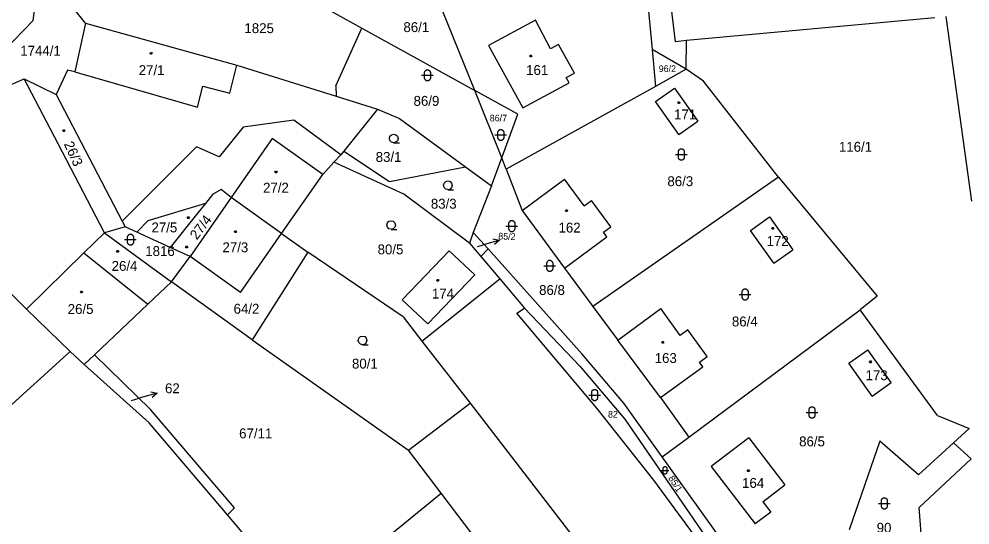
# Model space of a CAD drawing. Extents: x -799786 to -795190, y -1021716 to -1017834.
# Drawn here: x -797930.9 to -797767.7, y -1019141.2 to -1019054.3 of the extents above; entities that cross this region are included whole.
import ezdxf

# ---------------------------------------------------------------- set-up
doc = ezdxf.new("R2010")
doc.units = 0
for name, color, linetype in [('Default', 7, 'Continuous'), ('KN_HRANICE', 7, 'Continuous'), ('KN_KULTURY', 7, 'Continuous'), ('KN_PARCELY', 7, 'Continuous'), ('KN_SLUCKY', 7, 'Continuous')]:
    doc.layers.add(name, color=color, linetype=linetype)

# ---------------------------------------------------------------- blocks, each defined once
blk = doc.blocks.new('304')
at = {"layer": 'Default'}
blk.add_lwpolyline([(0, 0), (-0.38, 0.1), (-0.65, 0.37), (-0.75, 0.74), (-0.65, 1.11), (-0.38, 1.38), (-0.01, 1.48), (0.36, 1.38), (0.63, 1.11), (0.73, 0.73), (0.63, 0.35), (0.36, 0.08), (-0.02, -0.02), (0.98, -0.02)], dxfattribs=at)
blk = doc.blocks.new('316')
at = {"layer": 'Default'}
for points in [[(-0.5, 1.5), (-0.4, 1.79), (-0.15, 1.97), (0.16, 1.97), (0.41, 1.79), (0.51, 1.5), (0.51, 0.5), (0.41, 0.21), (0.16, 0.03), (-0.15, 0.03), (-0.4, 0.21), (-0.5, 0.5), (-0.5, 1.5)], [(-1, 1), (0.27, 1), (1, 1)]]:
    blk.add_lwpolyline(points, dxfattribs=at)
blk = doc.blocks.new('NAHRADNI_SYMBOL')
at = {"layer": 'Default'}
blk.add_lwpolyline([(0.09, 0.15), (0.18, 0), (0.09, -0.15), (-0.09, -0.15), (-0.18, 0), (-0.09, 0.15), (0.09, 0.15)], dxfattribs=at)
blk = doc.blocks.new('10292')
at = {"layer": 'Default'}
blk.add_line((0, 3), (0, 0), dxfattribs=at)
blk.add_lwpolyline([(-0.5, 2), (0, 3), (0.5, 2)], dxfattribs=at)
blk = doc.blocks.new('402')
at = {"layer": 'Default'}
blk.add_lwpolyline([(0.09, 0.15), (0.18, 0), (0.09, -0.15), (-0.09, -0.15), (-0.18, 0), (-0.09, 0.15), (0.09, 0.15)], dxfattribs=at)

msp = doc.modelspace()

# ---------------------------------------------------------------- linework, layer by layer
at = {"layer": 'KN_HRANICE'}
for p, q in [((-797852.67, -1019066.58), (-797869.05, -1019025.87)), ((-797818.22, -1019058.17), (-797821.18, -1019032.56)), ((-797928.48, -1019054.53), (-797927.24, -1019045.89)), ((-797823.64, -1019044.95), (-797822.2, -1019059.5)), ((-797883.29, -1019049.58), (-797872.02, -1019055.83)), ((-797919.48, -1019055.01), (-797921.61, -1019052.33)), ((-797842.24, -1019054.46), (-797850.27, -1019058.84)), ((-797839.67, -1019059.39), (-797842.24, -1019054.46)), ((-797773.7, -1019054.09), (-797816.3, -1019057.99)), ((-797767.35, -1019085.59), (-797771.72, -1019053.85)), ((-797933.64, -1019059.89), (-797928.48, -1019054.53)), ((-797919.48, -1019055.01), (-797921.28, -1019063.37)), ((-797919.48, -1019055.01), (-797893.51, -1019062.22)), ((-797876.5, -1019065.73), (-797872.02, -1019055.83)), ((-797872.02, -1019055.83), (-797852.67, -1019066.58)), ((-797850.27, -1019058.84), (-797844.43, -1019069.56)), ((-797838.26, -1019058.63), (-797839.67, -1019059.39)), ((-797835.56, -1019063.59), (-797838.26, -1019058.63)), ((-797816.3, -1019057.99), (-797818.22, -1019058.17)), ((-797816.38, -1019062.91), (-797816.3, -1019057.99)), ((-797816.38, -1019062.91), (-797822.2, -1019059.5)), ((-797822.2, -1019059.5), (-797821.66, -1019065.85)), ((-797893.51, -1019062.22), (-797876.43, -1019067.54)), ((-797922.55, -1019063.04), (-797924.49, -1019067.25)), ((-797921.28, -1019063.37), (-797922.55, -1019063.04)), ((-797836.96, -1019064.35), (-797835.56, -1019063.59)), ((-797816.38, -1019062.91), (-797821.66, -1019065.85)), ((-797813.4, -1019064.96), (-797816.38, -1019062.91)), ((-797942.17, -1019069.78), (-797930, -1019064.56)), ((-797930, -1019064.56), (-797924.49, -1019067.25)), ((-797924.18, -1019075.72), (-797930, -1019064.56)), ((-797876.5, -1019065.73), (-797876.43, -1019067.54)), ((-797821.66, -1019065.85), (-797847.25, -1019080.08)), ((-797844.43, -1019069.56), (-797836.48, -1019065.23)), ((-797836.48, -1019065.23), (-797836.96, -1019064.35)), ((-797800.54, -1019081.45), (-797813.4, -1019064.96)), ((-797924.49, -1019067.25), (-797913.17, -1019088.98)), ((-797845.27, -1019070.6), (-797852.67, -1019066.58)), ((-797848.03, -1019078.14), (-797852.67, -1019066.58)), ((-797821.62, -1019068.47), (-797818.35, -1019066.17)), ((-797818.35, -1019066.17), (-797814.38, -1019071.82)), ((-797876.43, -1019067.54), (-797869.33, -1019069.75)), ((-797817.65, -1019074.12), (-797821.62, -1019068.47)), ((-797869.33, -1019069.75), (-797875.15, -1019076.95)), ((-797869.33, -1019069.75), (-797865.57, -1019071.38)), ((-797848.03, -1019078.14), (-797845.27, -1019070.6)), ((-797883.72, -1019071.64), (-797892.43, -1019072.87)), ((-797875.67, -1019077.59), (-797883.72, -1019071.64)), ((-797865.57, -1019071.38), (-797854.22, -1019079.67)), ((-797817.65, -1019074.12), (-797814.38, -1019071.82)), ((-797892.43, -1019072.87), (-797896.5, -1019077.93)), ((-797916.22, -1019090.98), (-797924.18, -1019075.72)), ((-797900.41, -1019076.21), (-797913.17, -1019088.98)), ((-797896.5, -1019077.93), (-797900.41, -1019076.21)), ((-797875.15, -1019076.95), (-797875.67, -1019077.59)), ((-797878.76, -1019080.97), (-797876.83, -1019078.86)), ((-797876.83, -1019078.86), (-797875.67, -1019077.59)), ((-797864.84, -1019084.36), (-797876.83, -1019078.86)), ((-797849.78, -1019082.91), (-797848.03, -1019078.14)), ((-797847.25, -1019080.08), (-797848.03, -1019078.14)), ((-797854.22, -1019079.67), (-797849.78, -1019082.91)), ((-797847.25, -1019080.08), (-797844.54, -1019087.17)), ((-797885.82, -1019091.1), (-797878.76, -1019080.97)), ((-797844.54, -1019087.17), (-797837.24, -1019081.81)), ((-797833.88, -1019086.38), (-797837.24, -1019081.81)), ((-797800.54, -1019081.45), (-797832.38, -1019103.67)), ((-797800.54, -1019081.45), (-797783.57, -1019101.88)), ((-797896.16, -1019083.58), (-797897.65, -1019084.44)), ((-797894.47, -1019084.92), (-797896.16, -1019083.58)), ((-797849.78, -1019082.91), (-797852.91, -1019090.95)), ((-797894.47, -1019084.92), (-797901.53, -1019095.05)), ((-797897.65, -1019084.44), (-797898.89, -1019085.97)), ((-797885.82, -1019091.1), (-797894.47, -1019084.92)), ((-797853.58, -1019092.77), (-797864.84, -1019084.36)), ((-797833.88, -1019086.38), (-797832.59, -1019085.43)), ((-797829.28, -1019089.95), (-797832.59, -1019085.43)), ((-797898.89, -1019085.97), (-797908.77, -1019088.92)), ((-797898.89, -1019085.97), (-797900.18, -1019087.58)), ((-797900.18, -1019087.58), (-797904.91, -1019093.5)), ((-797844.54, -1019087.17), (-797837.27, -1019097.06)), ((-797805.32, -1019090.58), (-797802.05, -1019088.28)), ((-797802.05, -1019088.28), (-797798.08, -1019093.93)), ((-797912.66, -1019089.96), (-797916.22, -1019090.98)), ((-797913.17, -1019088.98), (-797912.66, -1019089.96)), ((-797910.68, -1019090.87), (-797912.66, -1019089.96)), ((-797910.68, -1019090.87), (-797908.77, -1019088.92)), ((-797830.57, -1019090.89), (-797829.28, -1019089.95)), ((-797916.22, -1019090.98), (-797919.74, -1019094.43)), ((-797916.22, -1019090.98), (-797904.71, -1019099.44)), ((-797904.91, -1019093.5), (-797910.68, -1019090.87)), ((-797892.88, -1019101.23), (-797885.82, -1019091.1)), ((-797885.82, -1019091.1), (-797881.32, -1019094.34)), ((-797852.91, -1019090.95), (-797853.58, -1019092.77)), ((-797850.38, -1019093.78), (-797852.91, -1019090.95)), ((-797837.27, -1019097.06), (-797829.98, -1019091.7)), ((-797829.98, -1019091.7), (-797830.57, -1019090.89)), ((-797801.35, -1019096.23), (-797805.32, -1019090.58)), ((-797901.53, -1019095.05), (-797904.91, -1019093.5)), ((-797853.58, -1019092.77), (-797851.62, -1019095.09)), ((-797919.74, -1019094.43), (-797929.59, -1019104.1)), ((-797919.74, -1019094.43), (-797908.76, -1019103.28)), ((-797904.71, -1019099.44), (-797901.53, -1019095.05)), ((-797892.88, -1019101.23), (-797901.53, -1019095.05)), ((-797881.32, -1019094.34), (-797890.88, -1019109.4)), ((-797864.94, -1019105.46), (-797881.32, -1019094.34)), ((-797857.07, -1019094.11), (-797865.14, -1019102.54)), ((-797852.66, -1019098.2), (-797857.07, -1019094.11)), ((-797851.62, -1019095.09), (-797850.38, -1019093.78)), ((-797851.62, -1019095.09), (-797848.38, -1019098.9)), ((-797834.2, -1019111.83), (-797850.38, -1019093.78)), ((-797801.35, -1019096.23), (-797798.08, -1019093.93)), ((-797852.66, -1019098.2), (-797860.73, -1019106.63)), ((-797837.27, -1019097.06), (-797832.38, -1019103.67)), ((-797934.34, -1019099.45), (-797929.59, -1019104.1)), ((-797904.71, -1019099.44), (-797908.76, -1019103.28)), ((-797890.88, -1019109.4), (-797904.71, -1019099.44)), ((-797861.73, -1019109.61), (-797848.38, -1019098.9)), ((-797848.38, -1019098.9), (-797844.12, -1019103.92)), ((-797908.76, -1019103.28), (-797917.9, -1019111.94)), ((-797860.73, -1019106.63), (-797865.14, -1019102.54)), ((-797783.57, -1019101.88), (-797786.49, -1019104.25)), ((-797929.59, -1019104.1), (-797922.11, -1019111.42)), ((-797845.41, -1019104.78), (-797844.12, -1019103.92)), ((-797831.7, -1019121.13), (-797845.41, -1019104.78)), ((-797844.12, -1019103.92), (-797834.61, -1019113.9)), ((-797832.38, -1019103.67), (-797828.1, -1019109.45)), ((-797828.1, -1019109.45), (-797820.73, -1019103.98)), ((-797817.38, -1019108.62), (-797820.73, -1019103.98)), ((-797815.93, -1019126.08), (-797786.49, -1019104.25)), ((-797773.22, -1019122.38), (-797786.49, -1019104.25)), ((-797864.94, -1019105.46), (-797861.73, -1019109.61)), ((-797816.08, -1019107.68), (-797817.38, -1019108.62)), ((-797812.78, -1019112.26), (-797816.08, -1019107.68)), ((-797890.88, -1019109.4), (-797864.05, -1019128.36)), ((-797861.73, -1019109.61), (-797853.47, -1019120.29)), ((-797820.8, -1019119.29), (-797828.1, -1019109.45)), ((-797939.64, -1019127.27), (-797922.11, -1019111.42)), ((-797919.69, -1019113.6), (-797922.11, -1019111.42)), ((-797788.43, -1019113.39), (-797785.16, -1019111.09)), ((-797781.19, -1019116.74), (-797785.16, -1019111.09)), ((-797917.9, -1019111.94), (-797919.69, -1019113.6)), ((-797908.3, -1019121.34), (-797917.9, -1019111.94)), ((-797827.05, -1019120.24), (-797834.2, -1019111.83)), ((-797814.08, -1019113.2), (-797812.78, -1019112.26)), ((-797813.49, -1019114.01), (-797814.08, -1019113.2)), ((-797908.56, -1019123.66), (-797919.69, -1019113.6)), ((-797834.61, -1019113.9), (-797826.91, -1019123.02)), ((-797820.8, -1019119.29), (-797813.49, -1019114.01)), ((-797784.46, -1019119.04), (-797788.43, -1019113.39)), ((-797784.46, -1019119.04), (-797781.19, -1019116.74)), ((-797820.8, -1019119.29), (-797815.93, -1019126.08)), ((-797893.87, -1019138.25), (-797908.3, -1019121.34)), ((-797864.05, -1019128.36), (-797853.47, -1019120.29)), ((-797853.47, -1019120.29), (-797769.25, -1019229.18)), ((-797821.92, -1019133.49), (-797831.7, -1019121.13)), ((-797820.48, -1019129.46), (-797827.05, -1019120.24)), ((-797826.91, -1019123.02), (-797788.58, -1019178.77)), ((-797773.22, -1019122.38), (-797767.81, -1019124.62)), ((-797895.08, -1019139.44), (-797908.56, -1019123.66)), ((-797767.81, -1019124.62), (-797770.51, -1019127.09)), ((-797820.48, -1019129.46), (-797815.93, -1019126.08)), ((-797805.6, -1019126.23), (-797812.06, -1019131.13)), ((-797805.6, -1019126.23), (-797799.46, -1019134.27)), ((-797783.1, -1019126.77), (-797788.38, -1019142.03)), ((-797776.48, -1019132.55), (-797783.1, -1019126.77)), ((-797770.51, -1019127.09), (-797776.48, -1019132.55)), ((-797767.46, -1019129.82), (-797770.51, -1019127.09)), ((-797858.44, -1019135.72), (-797864.05, -1019128.36)), ((-797787.5, -1019175.75), (-797820.48, -1019129.46)), ((-797812.06, -1019131.13), (-797804.51, -1019141.01)), ((-797776.38, -1019138.19), (-797767.46, -1019129.82)), ((-797788.58, -1019178.77), (-797821.92, -1019133.49)), ((-797803.2, -1019137.2), (-797799.46, -1019134.27)), ((-797881.99, -1019154.95), (-797858.44, -1019135.72)), ((-797814.48, -1019193.44), (-797858.44, -1019135.72)), ((-797803.2, -1019137.2), (-797801.84, -1019138.98)), ((-797895.08, -1019139.44), (-797893.87, -1019138.25)), ((-797801.84, -1019138.98), (-797804.51, -1019141.01)), ((-797775.5, -1019150.13), (-797776.38, -1019138.19)), ((-797881.99, -1019154.95), (-797895.08, -1019139.44))]:
    msp.add_line(p, q, dxfattribs=at)
msp.add_lwpolyline([(-797875.15, -1019076.95), (-797867.27, -1019082.18), (-797854.22, -1019079.67)], dxfattribs=at)
at = {"layer": 'KN_PARCELY'}
for p, q in [((-797852.2, -1019093.38), (-797851.31, -1019093.11)), ((-797911.6, -1019119.8), (-797910.07, -1019119.37))]:
    msp.add_line(p, q, dxfattribs=at)
at = {"layer": 'KN_SLUCKY'}
for p, q in [((-797894.69, -1019067.01), (-797893.51, -1019062.22)), ((-797921.28, -1019063.37), (-797900.22, -1019069.44)), ((-797900.22, -1019069.44), (-797899.31, -1019065.81)), ((-797899.31, -1019065.81), (-797894.69, -1019067.01)), ((-797887.41, -1019074.79), (-797894.47, -1019084.92)), ((-797878.76, -1019080.97), (-797887.41, -1019074.79))]:
    msp.add_line(p, q, dxfattribs=at)

# ---------------------------------------------------------------- block references
at = {"layer": 'KN_KULTURY'}
for name, p in [('402', (-797908.21, -1019060.19)), ('402', (-797843.05, -1019060.63)), ('316', (-797860.77, -1019064.95)), ('402', (-797817.61, -1019068.65)), ('NAHRADNI_SYMBOL', (-797923.2, -1019073.46)), ('304', (-797866.56, -1019075.53)), ('316', (-797848.2, -1019075.2)), ('316', (-797817.2, -1019078.56)), ('402', (-797886.77, -1019080.56)), ('304', (-797857.26, -1019083.58)), ('402', (-797836.89, -1019087.19)), ('NAHRADNI_SYMBOL', (-797901.82, -1019088.42)), ('304', (-797867, -1019090.4)), ('316', (-797846.3, -1019090.84)), ('402', (-797801.5, -1019090.22)), ('316', (-797911.76, -1019093.18)), ('402', (-797893.73, -1019090.8)), ('NAHRADNI_SYMBOL', (-797902.11, -1019093.43)), ('NAHRADNI_SYMBOL', (-797913.94, -1019094.17)), ('316', (-797839.79, -1019097.7)), ('402', (-797859.01, -1019099.17)), ('NAHRADNI_SYMBOL', (-797920.15, -1019101.19)), ('316', (-797806.26, -1019102.59)), ('304', (-797871.91, -1019110.22)), ('402', (-797820.38, -1019109.8)), ('402', (-797784.75, -1019113.17)), ('316', (-797832.08, -1019119.87)), ('316', (-797794.78, -1019122.88)), ('402', (-797805.7, -1019131.85)), ('316', (-797782.36, -1019138.48))]:
    msp.add_blockref(name, p, dxfattribs=at)
at = {"layer": 'KN_KULTURY', "xscale": 0.67, "yscale": 0.67}
msp.add_blockref('316', (-797820.01, -1019132.48), dxfattribs=at)
at = {"layer": 'KN_PARCELY'}
for p, rotation in [((-797851.31, -1019093.11), -73.406511), ((-797910.07, -1019119.37), -74.32324299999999)]:
    msp.add_blockref('10292', p, dxfattribs=dict(at, rotation=rotation))

# ---------------------------------------------------------------- texts
for s, height, p in [('1825', 1.7, (-797892.19, -1019056.7)), ('86/1', 1.7, (-797864.9, -1019056.52)), ('1744/1', 1.7, (-797930.66, -1019060.58)), ('27/1', 1.7, (-797910.33, -1019063.91)), ('161', 1.7, (-797843.84, -1019063.9)), ('96/2', 1.14, (-797821.08, -1019063.38)), ('86/9', 1.7, (-797863.16, -1019069.19)), ('86/7', 1.14, (-797850.08, -1019071.87)), ('171', 1.7, (-797818.44, -1019071.51)), ('116/1', 1.7, (-797790.15, -1019077.08)), ('83/1', 1.7, (-797869.66, -1019078.82)), ('86/3', 1.7, (-797819.59, -1019082.99)), ('27/2', 1.7, (-797888.99, -1019084.1)), ('83/3', 1.7, (-797860.19, -1019086.86)), ('27/5', 1.7, (-797908.14, -1019090.93)), ('162', 1.7, (-797838.28, -1019090.96)), ('172', 1.7, (-797802.56, -1019093.26)), ('1816', 1.7, (-797909.21, -1019094.99)), ('27/3', 1.7, (-797895.96, -1019094.34)), ('80/5', 1.7, (-797869.33, -1019094.7)), ('85/2', 0.1, (-797852.4, -1019093.38)), ('26/4', 1.7, (-797914.98, -1019097.54)), ('86/8', 1.7, (-797841.61, -1019101.68)), ('174', 1.7, (-797860.01, -1019102.3)), ('26/5', 1.7, (-797922.52, -1019104.94)), ('64/2', 1.7, (-797894.05, -1019104.9)), ('86/4', 1.7, (-797808.52, -1019107.08)), ('80/1', 1.7, (-797873.73, -1019114.33)), ('163', 1.7, (-797821.77, -1019113.37)), ('173', 1.7, (-797785.58, -1019116.32)), ('62', 1.7, (-797905.82, -1019118.56)), ('62', 0.1, (-797911.58, -1019119.8)), ('82', 1.14, (-797829.79, -1019122.75)), ('67/11', 1.7, (-797893.1, -1019126.31)), ('86/5', 1.7, (-797796.98, -1019127.69)), ('164', 1.7, (-797806.77, -1019134.82)), ('90', 1.7, (-797783.67, -1019142.52))]:
    msp.add_text(s, height=height, dxfattribs=at).set_placement(p)
for s, height, rotation, p in [('26/3', 1.7, 294.328, (-797923.22, -1019075.74)), ('27/4', 1.7, 52.884, (-797900.35, -1019092.31)), ('85/2', 1.14, 357.698, (-797848.64, -1019092.13)), ('85/1', 1.14, 302.751, (-797819.5, -1019133.17))]:
    msp.add_text(s, height=height, rotation=rotation, dxfattribs=at).set_placement(p)

doc.saveas('drawing.dxf')
